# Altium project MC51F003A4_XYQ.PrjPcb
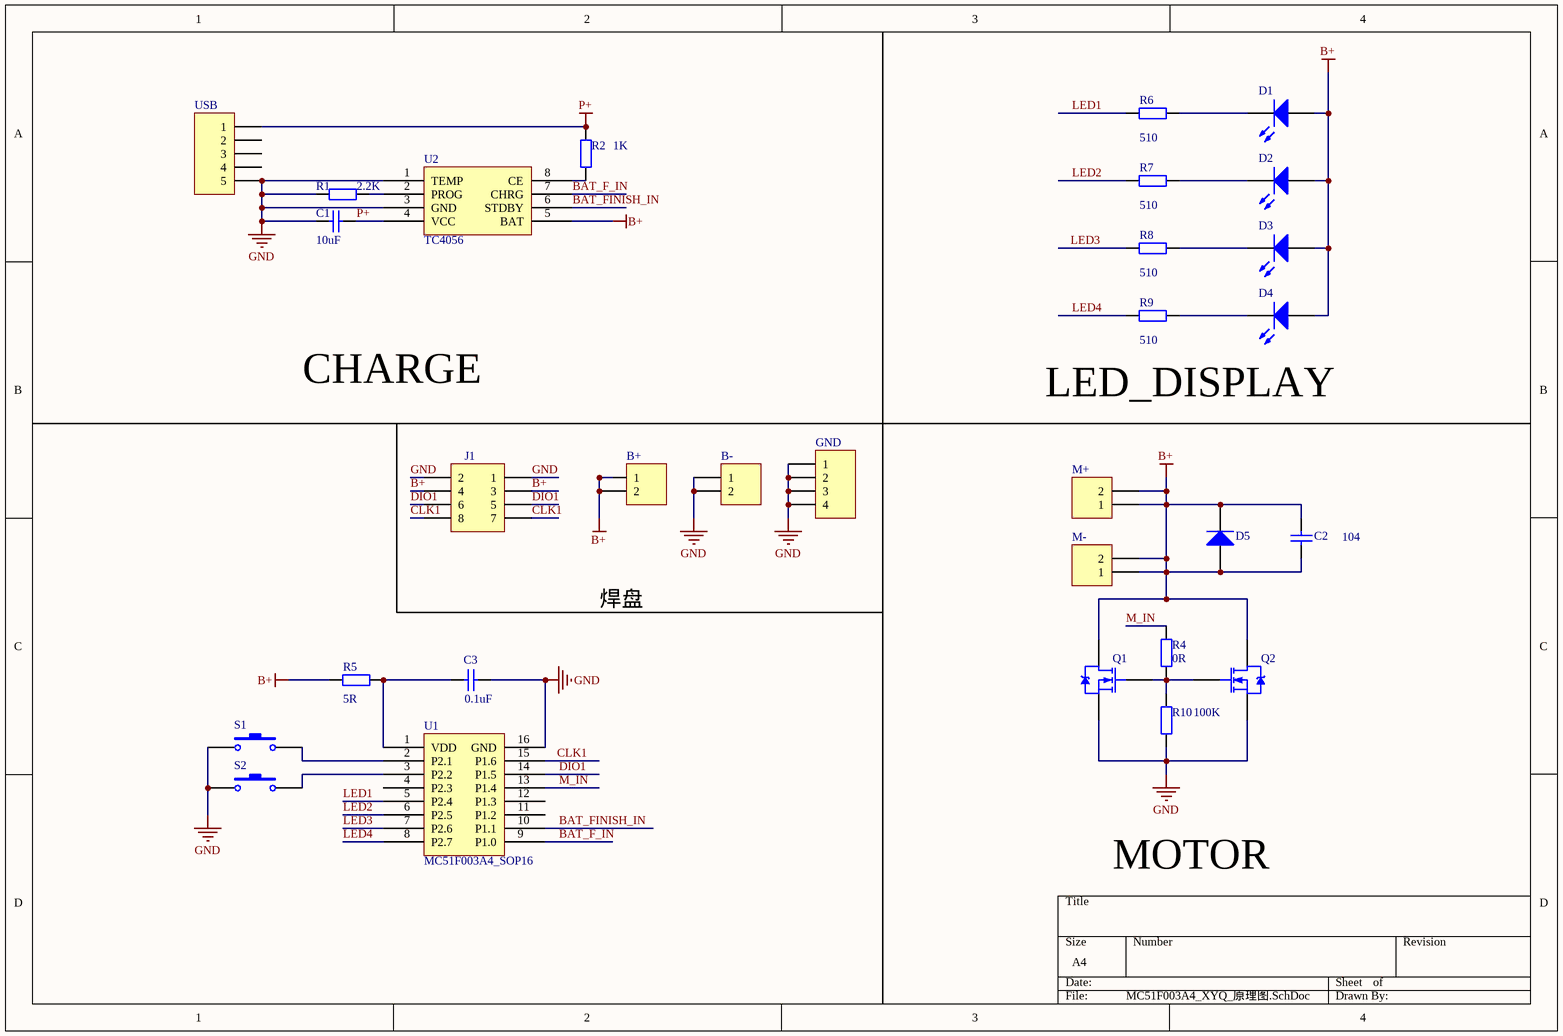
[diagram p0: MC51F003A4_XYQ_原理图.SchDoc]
1 sheet, 30 parts. Net scope: global (net labels, ports and power ports of the same name join across sheets).
Board file: MC51F003A4_XYQ_PCB.PcbDoc

## Sheet MC51F003A4_XYQ_原理图.SchDoc
size A4

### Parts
B+  MHDR1X2  [HDR1X2]  (value not drawn)
B-  MHDR1X2  [HDR1X2]  (value not drawn)
C1  value 10uF  [C0603]  (hidden comment: Cap)
C2  value 104  [C0603]  (hidden comment: Cap)
C3  value 0.1uF  [C0603]  (hidden comment: Cap)
D1  LED0  [LED0603-FD]  (value not drawn)
D2  LED0  [LED0603-FD]  (value not drawn)
D3  LED0  [LED0603-FD]  (value not drawn)
D4  LED0  [LED0603-FD]  (value not drawn)
D5  Diode  [SOD-123_L2.8-W1.8-LS3.7-RD]  (value not drawn)
GND  MHDR1X4  [HDR1X4]  (value not drawn)
J1  Header 4X2  [HDR2X4]  (value not drawn)
M+  Header 2  [HDR1X2]  (value not drawn)
M-  Header 2  [HDR1X2]  (value not drawn)
Q1  NMOS-2  [SOT-23-3_L2.9-W1.3-P1.90-LS2.4-BR]  (value not drawn)
Q2  NMOS-2  [SOT-23-3_L2.9-W1.3-P1.90-LS2.4-BR]  (value not drawn)
R1  value 2.2K  [R0603]  (hidden comment: Res2)
R2  value 1K  [R0603]  (hidden comment: Res2)
R4  value 0R  [R0603]  (hidden comment: Res2)
R5  value 5R  [R0603]  (hidden comment: Res2)
R6  value 510  [R0603]  (hidden comment: Res2)
R7  value 510  [R0603]  (hidden comment: Res2)
R8  value 510  [R0603]  (hidden comment: Res2)
R9  value 510  [R0603]  (hidden comment: Res2)
R10  value 100K  [R0603]  (hidden comment: Res2)
S1  SW-PB  [SW-SMD_4P-L6.0-W6.0-P4.50-LS10.0_UK-B0228XXX]  (value not drawn)
S2  SW-PB  [SW-SMD_4P-L6.0-W6.0-P4.50-LS10.0_UK-B0228XXX]  (value not drawn)
U1  MC51F003A4_SOP16  [SOP-16_L9.9-W3.9-P1.27-LS6.1-BL]
U2  TC4056  [SOP-8_L4.9-W3.9-P1.27-LS6.0-BL-EP]
USB  MHDR1X5  [MICRO-USB-SMD_MICRO-USB-A12]  (value not drawn)

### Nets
B+: B+.1 B+.2 C2.1 C2.2 D1.1(A) D2.1(A) D3.1(A) D4.1(A) D5.1(A) D5.2(K) J1.3 J1.4 M+.1 M+.2 M-.1 M-.2 Q1.3(D) Q2.3(D) R5.1 U2.5(BAT)
GND: B-.1 B-.2 C1.1 C3.2 GND.1 GND.2 GND.3 GND.4 J1.1 J1.2 Q1.2(S) Q2.2(S) R1.1 R10.1 S1.2 S2.4 U1.16(GND) U2.1(TEMP) U2.3(GND) USB.5
P+: C1.2 R2.2 U2.4(VCC) USB.1
BAT_F_IN: U1.9(P1.0) U2.7(CHRG)
BAT_FINISH_IN: U1.10(P1.1) U2.6(STDBY)
CLK1: J1.7 J1.8 U1.15(P1.6)
DIO1: J1.5 J1.6 U1.14(P1.5)
LED1: R6.2 U1.5(P2.4)
LED2: R7.2 U1.6(P2.5)
LED3: R8.2 U1.7(P2.6)
LED4: R9.1 U1.8(P2.7)
M_IN: R4.1 U1.13(P1.4)
NetC3_1: C3.1 R5.2 U1.1(VDD)
NetD1_2: D1.2(K) R6.1
NetD2_2: D2.2(K) R7.1
NetD3_2: D3.2(K) R8.1
NetD4_2: D4.2(K) R9.2
NetQ1_1: Q1.1(G) Q2.1(G) R4.2 R10.2
NetR1_2: R1.2 U2.2(PROG)
NetR2_1: R2.1 U2.8(CE)
NetS1_3: S1.3 U1.2(P2.1)
NetS2_1: S2.1 U1.3(P2.2)

Not connected (* = marked no-connect by the designer): U1 4(P2.3) 11(P1.2) 12(P1.3); USB 2 3 4

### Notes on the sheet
- CHARGE
- LED_DISPLAY
- 焊盘
- MOTOR

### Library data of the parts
B+ B- = MHDR1X2: Header, 2-Pin
C1-C3 = Cap: Capacitor
D1-D4 = LED0: Typical INFRARED GaAs LED
D5 = Diode: Default Diode
GND = MHDR1X4: Header, 4-Pin
J1 = Header 4X2: Header, 4-Pin, Dual row
M+ M- = Header 2: Header, 2-Pin
Q1 Q2 = NMOS-2: N-Channel Power MOSFET; Note: Pin 2 is electrically connected to pin 4.
R1 R2 R4-R10 = Res2: Resistor
S1 S2 = SW-PB: Switch
USB = MHDR1X5: Header, 5-Pin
